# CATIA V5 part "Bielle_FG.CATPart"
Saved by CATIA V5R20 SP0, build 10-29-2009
Part number: Bielle_FG
Bounding box of the stored display mesh (mm): x -4 to 7, y 79.102 to 128.166, z -3.997 to 67.47
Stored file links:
  D:\Dropbox\IAO_2012\IAO_2012_753_jrecappe\jrecappe.zip\Bielle_FG.CATPart
  D:\Dropbox\IAO_2012\IAO_2012_753_jrecappe\jrecappe.zip\Ass_brevetIAO_skl.CATProduct
  D:\Dropbox\IAO_2012\IAO_2012_753_jrecappe\jrecappe.zip\Ass_skl_levier2bras.CATProduct
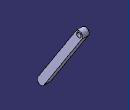
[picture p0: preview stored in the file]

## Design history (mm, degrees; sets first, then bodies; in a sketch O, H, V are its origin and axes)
Set1
  DatumPoint1 "Point F": linked copy from another document
  Point1 "Point G": linked copy from another document
Body1 (main body)
  Sketch1 on yz-plane, origin (0, 0, 0), H (0, 1, 0), V (0, 0, 1)
    construction line L1 (83.1, 0) -> (124.1671, 63.4733)
    point P1 (83.1, 0)
    point P2 (124.1671, 63.4733)
    line L2 (79.7416, 2.1729) -> (120.8087, 65.6461)
    line L3 (127.5254, 61.3004) -> (86.4584, -2.1729)
    arc A1 centre (124.1671, 63.4733) radius 4 from (120.8087, 65.6461) to (127.5254, 61.3004) cw
    arc A2 centre (83.1, 0) radius 4 from (86.4584, -2.1729) to (79.7416, 2.1729) cw
    reference projected point E1 (124.1671, 63.4733) from DatumPoint1
    reference projected point E2 (83.1, 0) from Point1
    distance L1 L2 = 4
    tangency: A1 L2, A2 L2, A1 L3, A2 L3
    coincidence: P2 E1, P1 E2
  Pad1: profile Sketch1, direction (1, 0, 0), length 7
  Sketch2 on yz-plane, origin (0, 0, 0), H (0, 1, 0), V (0, 0, 1)
    circle A1 centre (83.1, 0) radius 3
    point P1 (83.1, 0)
    reference projected point E1 (83.1, 0) from Point1
    coincidence: E1 P1
  Pad2: profile Sketch2, direction (1, 0, 0), length -4
  Sketch3 on yz-plane, origin (0, 0, 0), H (0, 1, 0), V (0, 0, 1)
    circle A1 centre (124.1671, 63.4733) radius 2.5
    point P1 (124.1671, 63.4733)
    reference projected point E1 (124.1671, 63.4733) from DatumPoint1
    coincidence: P1 E1
  Pocket1: profile Sketch3, direction (-1, 0, 0), length -8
